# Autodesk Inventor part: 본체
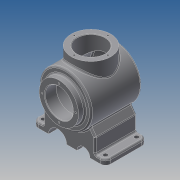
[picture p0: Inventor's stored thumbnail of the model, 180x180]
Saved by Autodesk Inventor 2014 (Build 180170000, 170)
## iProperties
Created: 2018-08
Part Number: 본체
Material: Generic
Document SubType Name: Modeling
Designer: kb542
Density: 1 g/cm^3
Appearance: Default
Author: kb542
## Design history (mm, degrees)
sketch "스케치1"
  geometry: L1 (-60, 0)-(60, 0); L2 (-60, 27)-(-60, 38); L3 (-60, 38)-(-48, 38); L4 (-48, 38)-(-48, 50); L5 (-48, 50)-(48.671, 50); L6 (-60, 27)-(-38, 27); L7 (-38, 27)-(-38, 40); L8 (-38, 40)-(42.163, 40); A1 r 116 centre (-56, 0) between (60, 0) and (48.671, 50); A2 r 106 centre (-56, 0) between (50, 0) and (42.163, 40); 3 further points
  constraints: 16 end point, 4 perpendicular, 4 point on circle, 3 parallel, 2 centre point, 2 midpoint, 2 point on line, 1 coincident, 1 horizontal, 1 vertical alignment
  dimensions: "d2" = 120 distance of L1.start L1.end; "d3" = 12 distance between parallel lines of L4 L2; "d5" = 76 diameter of L3 L1; "d6" = 100 diameter of L5 L1; "d7" = 54 diameter of L6 L1; "d8" = 80 diameter of L8 L1; "d9" = 22 distance between parallel lines of L7 L2; "d13" = 232 diameter of A1; "d14" = 10 radial gap between concentric circles of A1 A2
revolve "회전1" sketch "스케치1" stored, may be unused: angle "d15" = 90 deg
node "작업 평면1"
sketch "스케치2"
  geometry: L1 (50, -48)-(-50, -48) reference; C1 r 38 at (0, 2); 1 further point
  constraints: 1 centre point, 1 vertical alignment
  dimensions: "d17" = 50 distance from line of L1 C1.centre; "d18" = 76 diameter of C1
extrude "돌출1" join sketch "스케치2" stored distance "d19" = 10; taper "d20" = 0 deg
sketch "스케치3"
  geometry: C1 r 38 at (0, 0) reference; C2 r 27 at (0, 0); 1 further point
  constraints: 1 centre point, 1 coincident
  dimensions: "d21" = 54 diameter of C2
extrude "돌출2" cut sketch "스케치3" stored distance "d22" = 10; taper "d23" = 0 deg
node "작업 평면3"
  node "작업 평면2"
sketch "스케치4"
  geometry: L1 (-50, -43.437)-(-50, -72); L2 (-50, -72)-(-70, -72); L3 (-70, -72)-(-70, -82); L4 (-70, -82)-(70, -82); L5 (70, -82)-(70, -72); L6 (70, -72)-(50, -72); L7 (50, -72)-(50, -43.437); L8 (-70, -72)-(-40.304, -29.59); L9 (70, -72)-(40.304, -29.59); L10 (-50, -43.437)-(-40.304, -29.59); L11 (50, -43.437)-(40.304, -29.59); A1 r 50 centre (0, 0) between (-40.304, -29.59) and (40.304, -29.59) reference; A2 r 50 centre (0, 0) between (-40.304, -29.59) and (40.304, -29.59) reference; 2 further points
  constraints: 22 end point, 6 perpendicular, 4 point on circle, 2 collinear, 2 point on line, 1 midpoint, 1 vertical, 1 vertical alignment
  dimensions: "d27" = 20 distance of L1.end L2.end; "d29" = 20 distance of L5.end L6.end; "d30" = 82 distance from line of L4 point (0, 0); "d31" = 10 distance of L2.end L3.end; "d32" = 10 distance between parallel lines of L4 L6; "d33" = 140 distance of L3.end L4.end; "d39" = 35 deg angle of L9 L5; "d40" = 35 deg angle of L8 L3
extrude "돌출3" join sketch "스케치4" stored distance "d41" = 80; taper "d42" = 0 deg
node "작업 평면4"
sketch "스케치6"
  geometry: C1 r 50 at (0, 0) reference; C2 r 50 at (0, 0) reference; C3 r 32.5 at (0, 0); 1 further point
  constraints: 1 centre point, 1 coincident, 1 other
  dimensions: "d46" = 65 diameter of C3
feature "엠보싱2" sketch "스케치6" dims "d2" = 120, "d3" = 12, "d5" = 76, "d6" = 100, "d7" = 54, "d8" = 80, "d9" = 22, "d13" = 232, "d14" = 10, "d47" = 0.5, "d48" = 0
sketch "스케치7"
  geometry: L1 (70, 82)-(-70, 82) reference; L2 (-70, 72)-(-50, 72) reference; L3 (0, 0)-(0, 94.175); C1 r 12.5 at (27.5, 82); C2 r 17.5 at (-22.5, 82); A1 r 50 centre (0, 0) between (40.304, 29.59) and (-40.304, 29.59) reference
  constraints: 2 centre point, 2 end point, 2 point on line, 1 perpendicular
  dimensions: "d49" = 25 diameter of C1; "d50" = 35 diameter of C2; "d51" = 27.5 distance from line of L3 C1.centre; "d52" = 94.17488 distance of L3.start L3.end; "d53" = 22.5 distance from line of C2.centre L3
extrude "돌출4" cut sketch "스케치7" stored distance "d54" = 80; taper "d55" = 0 deg
fillet "모깎기1" dims "d56" = 10
sketch "스케치8"
  geometry: L1 (-120, 70)-(-120, 10) reference; L2 (-100, 0)-(-110, 0) reference; L3 (-100, 80)-(-100, 0) reference; L4 (-110, 80)-(-100, 80) reference; A1 r 10 centre (10, 70) between (20, 70) and (10, 80) reference; A2 r 10 centre (10, 10) between (10, 0) and (20, 10) reference; A3 r 10 centre (-110, 70) between (-110, 80) and (-120, 70) reference; A4 r 10 centre (-110, 10) between (-120, 10) and (-110, 0) reference; 5 further points
  constraints: 4 coincident
hole "구멍1" sketch "스케치8" at (10, 70), (10, 10), (-110, 10), (-110, 70) diameter "d57" = 8; stored, may be unused: countersink angle "d61" = 90 deg, drill point angle "d63" = 118 deg; dims "d58" = 6, "d59" = 4, "d60" = 2, "d62" = 8
sketch "스케치9"
  geometry: C1 r 38 at (0, 0) reference; A1 r 32.5 centre (0, 0) between (0, 32.5) and (32.5, 0); 2 further points
  constraints: 4 point on circle, 2 horizontal alignment, 2 vertical alignment, 1 centre point, 1 coincident
  dimensions: "d64" = 65 diameter of A1
hole "구멍2" sketch "스케치9" at (0, 32.5), (32.5, 0), (0, -32.5), (-32.5, 0) diameter "d65" = 3.242; stored, may be unused: countersink angle "d69" = 90 deg, drill point angle "d71" = 118 deg; dims "d66" = 8, "d67" = 4, "d68" = 2, "d70" = 10
sketch "스케치10"
  geometry: C1 r 27 at (0, 0) reference; C2 r 38 at (0, 0) reference; A1 r 32.5 centre (0, 0) between (0, 32.5) and (32.5, 0); 3 further points
  constraints: 4 point on circle, 2 horizontal alignment, 2 vertical alignment, 1 centre point, 1 coincident
  dimensions: "d72" = 65 diameter of A1
hole "구멍3" sketch "스케치10" at (0, 32.5), (32.5, 0), (0, -32.5), (-32.5, 0) diameter "d73" = 3.242; stored, may be unused: countersink angle "d77" = 90 deg, drill point angle "d79" = 118 deg; dims "d74" = 8, "d75" = 4, "d76" = 2, "d78" = 10
fillet "모깎기2" dims "d80" = 3
fillet "모깎기3" dims "d81" = 3
fillet "모깎기4" dims "d82" = 3
chamfer "모따기1" distance "d83" = 1; stored, may be unused: second distance "d84" = 2, angle "d85" = 45 deg
fillet "모깎기5" dims "d86" = 3
node "솔리드1"
node "투영된 루프1"
node "투영된 루프2"
node "투영된 루프3"
other parameters: "d16" = 65, "d24" = -54
